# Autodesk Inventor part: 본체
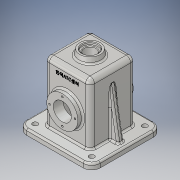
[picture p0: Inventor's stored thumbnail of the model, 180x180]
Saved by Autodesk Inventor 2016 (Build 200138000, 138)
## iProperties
Created: 2022-11
Part Number: 본체
Material: 알루미늄 6061
Document SubType Name: Modeling
Designer: CAD03
Density: 2.7 g/cm^3
Appearance: 알루미늄 - 평지
Mass: 1130.08 g
Surface Area: 1016.68 cm^2
Volume: 418.546 cm^3
Author: CAD03
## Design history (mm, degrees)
node "작업 평면1"
sketch "스케치1"
  geometry: L1 (-40, 40)-(40, 40); L2 (40, 40)-(40, -40); L3 (40, -40)-(-40, -40); L4 (-40, -40)-(-40, 40); L5 (-40, 40)-(40, -40); L6 (40, 40)-(-40, -40); 1 further point
  constraints: 12 end point, 2 midpoint, 2 parallel, 1 horizontal, 1 perpendicular
  dimensions: "d1" = 80 distance of L2.end L3.end; "d2" = 80 distance of L1.end L2.end
extrude "돌출1" new body sketch "스케치1" distance "d3" = 117; taper "d4" = 0 deg
fillet "모깎기1" dims "d5" = 8
fillet "모깎기2" dims "d6" = 8
feature "쉘1" dims "d7" = 8
fillet "모깎기3" dims "d8" = 3
fillet "모깎기4" dims "d9" = 3
sketch "스케치2"
  geometry: L1 (-65, 62)-(65, 62); L2 (65, 62)-(65, -62); L3 (65, -62)-(-65, -62); L4 (-65, -62)-(-65, 62); L5 (-65, 62)-(65, -62); L6 (65, 62)-(-65, -62); L7 (-29, -32)-(29, -32) reference; L8 (32, -29)-(32, 29) reference; L9 (29, 32)-(-29, 32) reference; L10 (-32, 29)-(-32, -29) reference; L11 (32, -40)-(-32, -40) reference; L12 (-40, -32)-(-40, 32) reference; L13 (-32, 40)-(32, 40) reference; L14 (40, 32)-(40, -32) reference; A1 r 3 centre (29, -29) between (29, -32) and (32, -29) reference; A2 r 3 centre (29, 29) between (32, 29) and (29, 32) reference; A3 r 3 centre (-29, 29) between (-29, 32) and (-32, 29) reference; A4 r 3 centre (-29, -29) between (-32, -29) and (-29, -32) reference; A5 r 8 centre (32, -32) between (32, -40) and (40, -32) reference; A6 r 8 centre (-32, -32) between (-40, -32) and (-32, -40) reference; A7 r 8 centre (-32, 32) between (-32, 40) and (-40, 32) reference; A8 r 8 centre (32, 32) between (40, 32) and (32, 40) reference; 1 further point
  constraints: 12 end point, 2 midpoint, 2 parallel, 1 horizontal, 1 perpendicular
  dimensions: "d10" = 130 distance of L2.end L3.end; "d11" = 124 distance of L1.end L2.end
extrude "돌출3" join sketch "스케치2" distance "d16" = 10; taper "d17" = 0 deg
fillet "모깎기7" dims "d18" = 15
hole "구멍1" diameter "d21" = 9; stored, may be unused: countersink angle "d25" = 90 deg, drill point angle "d27" = 0 deg; dims "d19" = 10, "d20" = 10, "d22" = 6, "d23" = 4, "d24" = 2, "d26" = 8
fillet "모깎기8" dims "d34" = 3
sketch "스케치3"
  geometry: L1 (82, -109)-(-18, -109) reference; C1 r 27.5 at (32, -54); 1 further point
  constraints: 1 centre point, 1 coincident
  dimensions: "d37" = 55 diameter of C1; "d38" = 55 distance from line of L1 C1.centre
extrude "돌출4" join sketch "스케치3" distance "d39" = 9; taper "d40" = 0 deg
hole "구멍2" diameter "d43" = 32; stored, may be unused: countersink angle "d47" = 90 deg, drill point angle "d49" = 0 deg; dims "d41" = 10, "d42" = 10, "d44" = 6, "d45" = 4, "d46" = 2, "d48" = 8
fillet "모깎기9" dims "d50" = 3
sketch "스케치4"
  geometry: L1 (0, 0)-(0, 22.5)
  constraints: 2 end point, 1 vertical
  dimensions: "d51" = 22.5 distance of L1.start L1.end
hole "구멍3" sketch "스케치4" at (0, 22.5) diameter "d52" = 3.242; stored, may be unused: countersink angle "d56" = 90 deg, drill point angle "d58" = 118 deg; dims "d53" = 8, "d54" = 4, "d55" = 2, "d57" = 10
sketch "스케치5"
  geometry: L1 (65, -55)-(65, -48) reference; L2 (50, -45)-(62, -45) reference; L3 (-55, -45)-(-40, 40.069); L4 (-62, -45)-(-50, -45) reference; L5 (-65, -48)-(-65, -55) reference; L6 (-40, 54)-(-40, -45) reference; 1 further point
  constraints: 2 end point, 2 point on line
  dimensions: "d64" = 100 deg angle of L4 L3; "d65" = 10 distance from line of L5 L3.start
feature "리브1" sketch "스케치5" dims "d66" = 1, "d67" = 10, "d68" = 0, "d69" = 0, "d70" = 1, "d71" = 1
fillet "모깎기10" dims "d72" = 3
fillet "모깎기11" dims "d73" = 3
fillet "모깎기12" dims "d74" = 3
sketch "스케치6"
  geometry: C1 r 20 at (0, 0); 1 further point
  constraints: 1 centre point, 1 coincident
  dimensions: "d76" = 40 diameter of C1
extrude "돌출5" join sketch "스케치6" distance "d77" = 10; taper "d78" = -10 deg
fillet "모깎기13" dims "d79" = 3
hole "구멍4" diameter "d82" = 21; stored, may be unused: countersink angle "d86" = 90 deg, drill point angle "d88" = 0 deg; dims "d80" = 10, "d81" = 10, "d83" = 8, "d84" = 28, "d85" = 4, "d87" = 10
chamfer "모따기1" distance "d89" = 1; stored, may be unused: second distance "d90" = 2, angle "d91" = 45 deg
node "작업 평면3"
sketch "스케치7"
  geometry: L1 (-18.237, 72)-(18.237, 72) reference; L2 (40, -42)-(40, 54) reference; 2 further points
  constraints: 1 other
  dimensions: "d93" = 25 distance from line of point (0, 47) L1; "d94" = 40 distance from line of L2 point (0, 47)
feature "엠보싱1" sketch "스케치7" dims "d95" = 0.5, "d96" = 0
node "솔리드1"
pattern_linear "직사각형 패턴1" dims "d30" = 100, "d33" = 94
mirror "대칭1"
pattern_circular "원형 패턴1" dims angle "d60" = 360 deg
mirror "대칭2"
mirror "대칭3"
node "투영된 루프1"
other parameters: "d0" = -55
